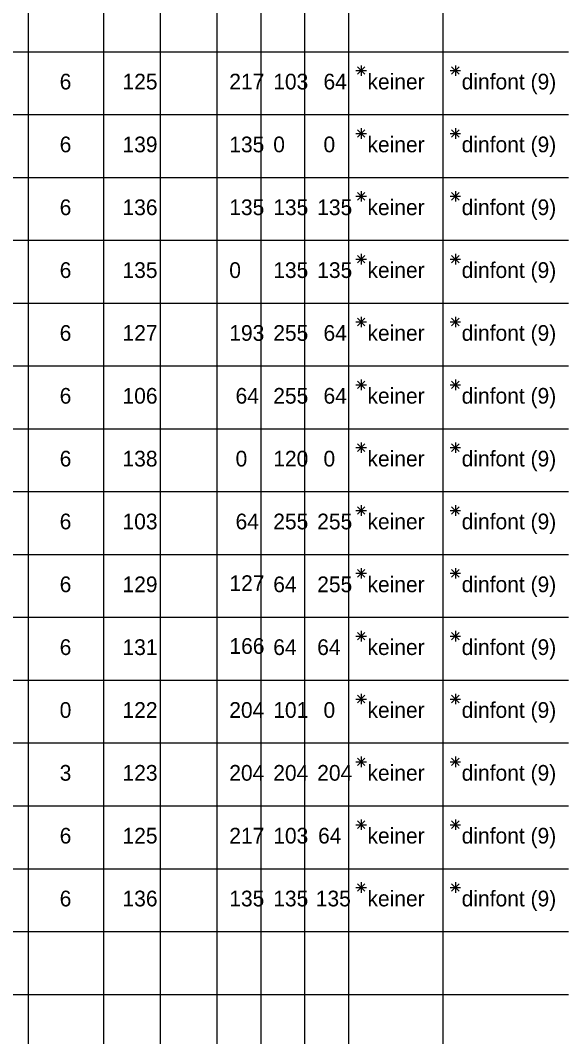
# Model space of a CAD drawing. Extents: x -14.5 to 23.8, y -56.3 to 8.
# Drawn here: x 11.64 to 15.95, y -31.84 to -23.75 of the extents above; entities that cross this region are included whole.
import ezdxf

# ---------------------------------------------------------------- set-up
doc = ezdxf.new("R2010")
doc.units = 0
doc.layers.add('Default', color=7, linetype='Continuous')

msp = doc.modelspace()

# ---------------------------------------------------------------- linework, layer by layer
at = {"layer": 'Default'}
for p, q in [((11.7, -0.35), (11.7, -44.5)), ((12.3, -0.35), (12.3, -44.5)), ((12.75, -0.35), (12.75, -44.5)), ((13.2, -0.35), (13.2, -44.5)), ((14.25, -0.35), (14.25, -48)), ((15, -0.35), (15, -48)), ((13.55, -0.75), (13.55, -44.5)), ((13.9, -0.75), (13.9, -44.5)), ((0, -24), (16, -24)), ((14.3081, -24.15), (14.3919, -24.15)), ((14.3203, -24.1203), (14.3797, -24.1797)), ((14.3797, -24.1203), (14.3203, -24.1797)), ((14.35, -24.1081), (14.35, -24.1919)), ((15.0581, -24.15), (15.1419, -24.15)), ((15.0703, -24.1203), (15.1297, -24.1797)), ((15.1297, -24.1203), (15.0703, -24.1797)), ((15.1, -24.1081), (15.1, -24.1919)), ((0, -24.5), (16, -24.5)), ((14.3081, -24.65), (14.3919, -24.65)), ((14.3203, -24.6203), (14.3797, -24.6797)), ((14.3797, -24.6203), (14.3203, -24.6797)), ((14.35, -24.6081), (14.35, -24.6919)), ((15.0581, -24.65), (15.1419, -24.65)), ((15.0703, -24.6203), (15.1297, -24.6797)), ((15.1297, -24.6203), (15.0703, -24.6797)), ((15.1, -24.6081), (15.1, -24.6919)), ((0, -25), (16, -25)), ((14.3203, -25.1203), (14.3797, -25.1797)), ((14.3797, -25.1203), (14.3203, -25.1797)), ((14.35, -25.1081), (14.35, -25.1919)), ((15.0703, -25.1203), (15.1297, -25.1797)), ((15.1297, -25.1203), (15.0703, -25.1797)), ((15.1, -25.1081), (15.1, -25.1919)), ((14.3081, -25.15), (14.3919, -25.15)), ((15.0581, -25.15), (15.1419, -25.15)), ((0, -25.5), (16, -25.5)), ((14.3203, -25.6203), (14.3797, -25.6797)), ((14.3797, -25.6203), (14.3203, -25.6797)), ((14.35, -25.6081), (14.35, -25.6919)), ((15.0703, -25.6203), (15.1297, -25.6797)), ((15.1297, -25.6203), (15.0703, -25.6797)), ((15.1, -25.6081), (15.1, -25.6919)), ((14.3081, -25.65), (14.3919, -25.65)), ((15.0581, -25.65), (15.1419, -25.65)), ((0, -26), (16, -26)), ((14.35, -26.1081), (14.35, -26.1919)), ((15.1, -26.1081), (15.1, -26.1919)), ((14.3081, -26.15), (14.3919, -26.15)), ((14.3203, -26.1203), (14.3797, -26.1797)), ((14.3797, -26.1203), (14.3203, -26.1797)), ((15.0581, -26.15), (15.1419, -26.15)), ((15.0703, -26.1203), (15.1297, -26.1797)), ((15.1297, -26.1203), (15.0703, -26.1797)), ((0, -26.5), (16, -26.5)), ((14.3081, -26.65), (14.3919, -26.65)), ((14.3203, -26.6203), (14.3797, -26.6797)), ((14.3797, -26.6203), (14.3203, -26.6797)), ((14.35, -26.6081), (14.35, -26.6919)), ((15.0581, -26.65), (15.1419, -26.65)), ((15.0703, -26.6203), (15.1297, -26.6797)), ((15.1297, -26.6203), (15.0703, -26.6797)), ((15.1, -26.6081), (15.1, -26.6919)), ((0, -27), (16, -27)), ((14.3081, -27.15), (14.3919, -27.15)), ((14.3203, -27.1203), (14.3797, -27.1797)), ((14.3797, -27.1203), (14.3203, -27.1797)), ((14.35, -27.1081), (14.35, -27.1919)), ((15.0581, -27.15), (15.1419, -27.15)), ((15.0703, -27.1203), (15.1297, -27.1797)), ((15.1297, -27.1203), (15.0703, -27.1797)), ((15.1, -27.1081), (15.1, -27.1919)), ((0, -27.5), (16, -27.5)), ((14.3081, -27.65), (14.3919, -27.65)), ((14.3203, -27.6203), (14.3797, -27.6797)), ((14.3797, -27.6203), (14.3203, -27.6797)), ((14.35, -27.6081), (14.35, -27.6919)), ((15.0581, -27.65), (15.1419, -27.65)), ((15.0703, -27.6203), (15.1297, -27.6797)), ((15.1297, -27.6203), (15.0703, -27.6797)), ((15.1, -27.6081), (15.1, -27.6919)), ((0, -28), (16, -28)), ((14.3203, -28.1203), (14.3797, -28.1797)), ((14.3797, -28.1203), (14.3203, -28.1797)), ((14.35, -28.1081), (14.35, -28.1919)), ((15.0703, -28.1203), (15.1297, -28.1797)), ((15.1297, -28.1203), (15.0703, -28.1797)), ((15.1, -28.1081), (15.1, -28.1919)), ((14.3081, -28.15), (14.3919, -28.15)), ((15.0581, -28.15), (15.1419, -28.15)), ((0, -28.5), (16, -28.5)), ((14.3203, -28.6203), (14.3797, -28.6797)), ((14.3797, -28.6203), (14.3203, -28.6797)), ((14.35, -28.6081), (14.35, -28.6919)), ((15.0703, -28.6203), (15.1297, -28.6797)), ((15.1297, -28.6203), (15.0703, -28.6797)), ((15.1, -28.6081), (15.1, -28.6919)), ((14.3081, -28.65), (14.3919, -28.65)), ((15.0581, -28.65), (15.1419, -28.65)), ((0, -29), (16, -29)), ((14.35, -29.1081), (14.35, -29.1919)), ((15.1, -29.1081), (15.1, -29.1919)), ((14.3081, -29.15), (14.3919, -29.15)), ((14.3203, -29.1203), (14.3797, -29.1797)), ((14.3797, -29.1203), (14.3203, -29.1797)), ((15.0581, -29.15), (15.1419, -29.15)), ((15.0703, -29.1203), (15.1297, -29.1797)), ((15.1297, -29.1203), (15.0703, -29.1797)), ((0, -29.5), (16, -29.5)), ((14.3081, -29.65), (14.3919, -29.65)), ((14.3203, -29.6203), (14.3797, -29.6797)), ((14.3797, -29.6203), (14.3203, -29.6797)), ((14.35, -29.6081), (14.35, -29.6919)), ((15.0581, -29.65), (15.1419, -29.65)), ((15.0703, -29.6203), (15.1297, -29.6797)), ((15.1297, -29.6203), (15.0703, -29.6797)), ((15.1, -29.6081), (15.1, -29.6919)), ((0, -30), (16, -30)), ((14.3081, -30.15), (14.3919, -30.15)), ((14.3203, -30.1203), (14.3797, -30.1797)), ((14.3797, -30.1203), (14.3203, -30.1797)), ((14.35, -30.1081), (14.35, -30.1919)), ((15.0581, -30.15), (15.1419, -30.15)), ((15.0703, -30.1203), (15.1297, -30.1797)), ((15.1297, -30.1203), (15.0703, -30.1797)), ((15.1, -30.1081), (15.1, -30.1919)), ((0, -30.5), (16, -30.5)), ((14.3203, -30.6203), (14.3797, -30.6797)), ((14.3797, -30.6203), (14.3203, -30.6797)), ((14.35, -30.6081), (14.35, -30.6919)), ((15.0703, -30.6203), (15.1297, -30.6797)), ((15.1297, -30.6203), (15.0703, -30.6797)), ((15.1, -30.6081), (15.1, -30.6919)), ((14.3081, -30.65), (14.3919, -30.65)), ((15.0581, -30.65), (15.1419, -30.65)), ((0, -31), (16, -31)), ((0, -31.5), (16, -31.5))]:
    msp.add_line(p, q, dxfattribs=at)

# ---------------------------------------------------------------- texts
for s, p in [('6', (11.95, -24.3)), ('125', (12.45, -24.3)), ('217', (13.3, -24.3)), ('103', (13.65, -24.3)), ('64', (14.05, -24.3)), ('keiner', (14.4, -24.3)), ('dinfont (9)', (15.15, -24.3)), ('6', (11.95, -24.8)), ('139', (12.45, -24.8)), ('135', (13.3, -24.8)), ('0', (13.65, -24.8)), ('0', (14.05, -24.8)), ('keiner', (14.4, -24.8)), ('dinfont (9)', (15.15, -24.8)), ('6', (11.95, -25.3)), ('136', (12.45, -25.3)), ('135', (13.3, -25.3)), ('135', (13.65, -25.3)), ('135', (14, -25.3)), ('keiner', (14.4, -25.3)), ('dinfont (9)', (15.15, -25.3)), ('6', (11.95, -25.8)), ('135', (12.45, -25.8)), ('0', (13.3, -25.8)), ('135', (13.65, -25.8)), ('135', (14, -25.8)), ('keiner', (14.4, -25.8)), ('dinfont (9)', (15.15, -25.8)), ('6', (11.95, -26.3)), ('127', (12.45, -26.3)), ('193', (13.3, -26.3)), ('255', (13.65, -26.3)), ('64', (14.05, -26.3)), ('keiner', (14.4, -26.3)), ('dinfont (9)', (15.15, -26.3)), ('6', (11.95, -26.8)), ('106', (12.45, -26.8)), ('64', (13.35, -26.8)), ('255', (13.65, -26.8)), ('64', (14.05, -26.8)), ('keiner', (14.4, -26.8)), ('dinfont (9)', (15.15, -26.8)), ('keiner', (14.4, -27.3)), ('dinfont (9)', (15.15, -27.3)), ('6', (11.95, -27.3)), ('138', (12.45, -27.3)), ('0', (13.35, -27.3)), ('120', (13.65, -27.3)), ('0', (14.05, -27.3)), ('6', (11.95, -27.8)), ('103', (12.45, -27.8)), ('64', (13.35, -27.8)), ('255', (13.65, -27.8)), ('255', (14, -27.8)), ('keiner', (14.4, -27.8)), ('dinfont (9)', (15.15, -27.8)), ('6', (11.95, -28.3)), ('129', (12.45, -28.3)), ('127', (13.3014, -28.2907)), ('64', (13.65, -28.3)), ('255', (14, -28.3)), ('keiner', (14.4, -28.3)), ('dinfont (9)', (15.15, -28.3)), ('6', (11.95, -28.8)), ('131', (12.45, -28.8)), ('166', (13.3014, -28.7907)), ('64', (13.65, -28.8)), ('64', (14, -28.8)), ('keiner', (14.4, -28.8)), ('dinfont (9)', (15.15, -28.8)), ('0', (11.95, -29.3)), ('122', (12.45, -29.3)), ('204', (13.3, -29.3)), ('101', (13.65, -29.3)), ('0', (14.05, -29.3)), ('keiner', (14.4, -29.3)), ('dinfont (9)', (15.15, -29.3)), ('3', (11.95, -29.8)), ('123', (12.45, -29.8)), ('204', (13.3, -29.8)), ('204', (13.65, -29.8)), ('204', (14, -29.8)), ('keiner', (14.4, -29.8)), ('dinfont (9)', (15.15, -29.8)), ('6', (11.95, -30.3)), ('125', (12.45, -30.3)), ('217', (13.3, -30.3)), ('103', (13.65, -30.3)), ('64', (14.007, -30.3)), ('keiner', (14.4, -30.3)), ('dinfont (9)', (15.15, -30.3)), ('6', (11.95, -30.8)), ('136', (12.45, -30.8)), ('135', (13.3, -30.8)), ('135', (13.65, -30.8)), ('135', (13.9886, -30.8)), ('keiner', (14.4, -30.8)), ('dinfont (9)', (15.15, -30.8))]:
    msp.add_text(s, height=0.125, dxfattribs=at).set_placement(p)

doc.saveas('drawing.dxf')
